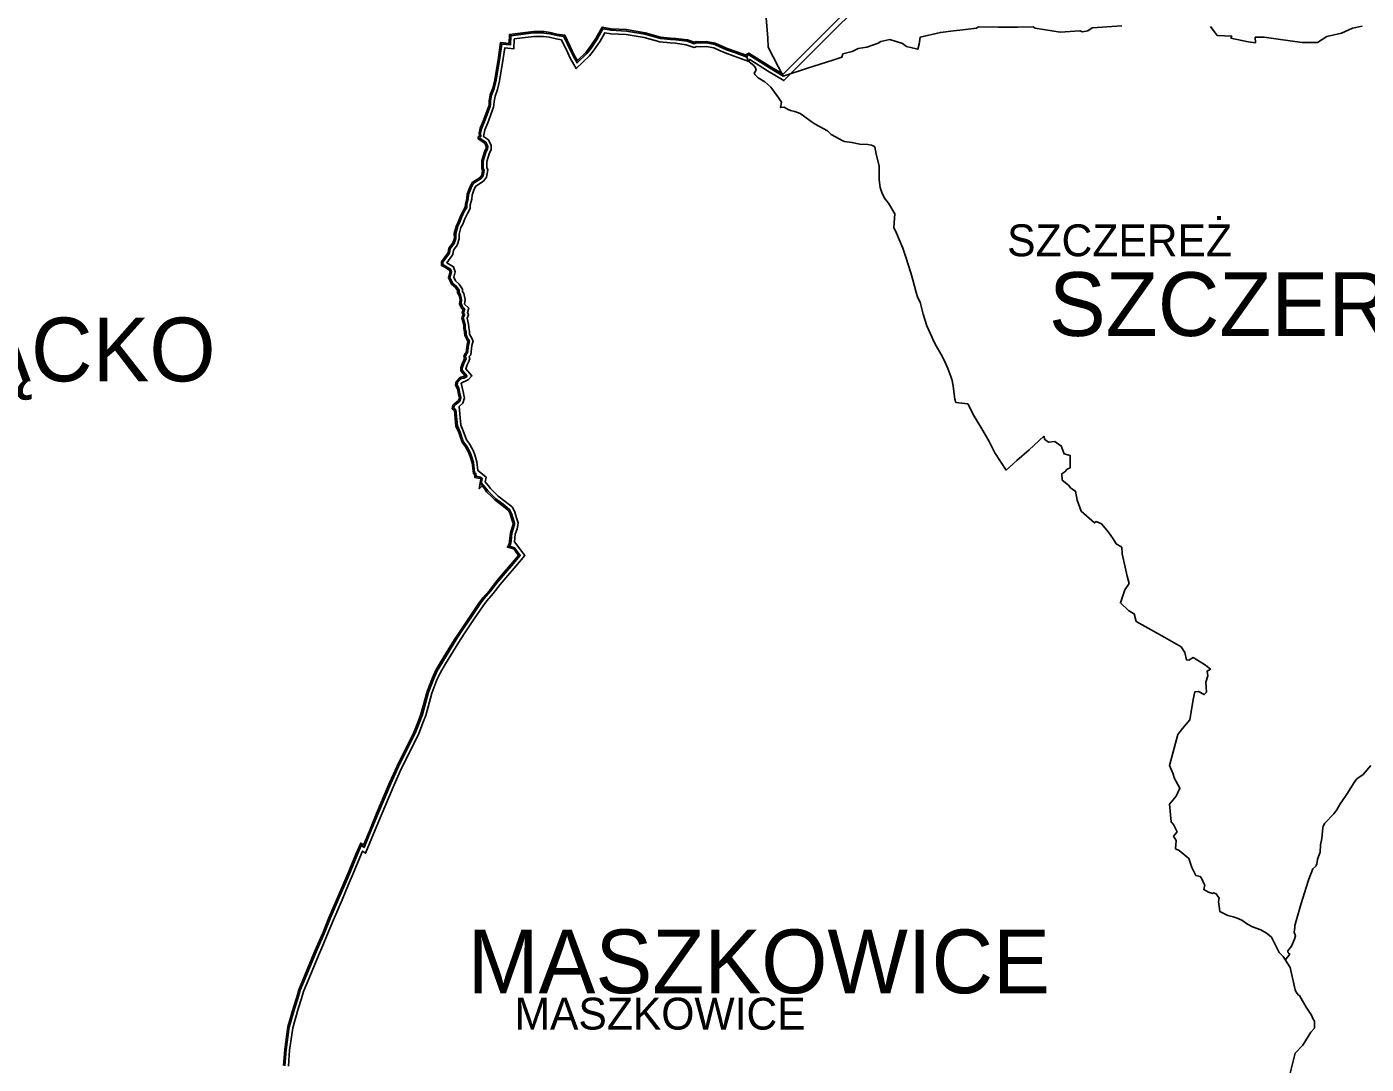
# Model space of a CAD drawing. Extents: x -562952 to -547638, y 190691 to 208158.
# Drawn here: x -556696 to -552912, y 199380 to 202309 of the extents above; entities that cross this region are included whole.
import ezdxf

# ---------------------------------------------------------------- set-up
doc = ezdxf.new("R2010")
doc.units = 0
for name, color, linetype in [('granica A_B', 7, 'Continuous'), ('granica_gminy', 7, 'Continuous'), ('granica_sołectwa', 7, 'Continuous'), ('nazwy miejscowości', 7, 'Continuous'), ('nazwy miejscowości DUŻE', 7, 'Continuous'), ('obwódka', 7, 'Continuous')]:
    doc.layers.add(name, color=color, linetype=linetype)

msp = doc.modelspace()

# ---------------------------------------------------------------- linework, layer by layer
at = {"layer": 'granica A_B'}
for points in [[(-555970.3, 199376.4), (-555967.1, 199421.4), (-555961.2, 199464.8), (-555958.2, 199485.8), (-555942.4, 199540.2), (-555933, 199569.1), (-555927.3, 199590), (-555909.1, 199633.1), (-555884.5, 199692.2), (-555872.4, 199720.8), (-555859.7, 199750.4), (-555842.2, 199793.3), (-555817.9, 199849.8), (-555800.4, 199891.1), (-555786.3, 199923.9), (-555765.3, 199974.4), (-555752.5, 200004.2), (-555744.8, 199998), (-555729, 200036), (-555708, 200087.9), (-555683.9, 200143.4), (-555671, 200174.2), (-555649.4, 200221.9), (-555630.3, 200260.3), (-555613, 200295.4), (-555602, 200316.1), (-555589.7, 200349.1), (-555582.2, 200368.6), (-555564.9, 200431.9), (-555550, 200470.8), (-555539.8, 200492.4), (-555525.4, 200517.5), (-555487.1, 200579.5), (-555471.8, 200602.5), (-555443.2, 200645.3), (-555418.4, 200681.8), (-555407.4, 200696.7), (-555388.8, 200717.8), (-555369, 200743.4), (-555347.7, 200768.8), (-555329.5, 200789.7), (-555306.9, 200816.6), (-555320.3, 200834.6), (-555338.2, 200839.7), (-555333, 200848.4), (-555331.9, 200857.8), (-555329.8, 200879.6), (-555324.3, 200895.7), (-555322.2, 200904.7), (-555321.9, 200906.8), (-555325.9, 200918.3), (-555329.9, 200933.4), (-555335.2, 200943.7), (-555352.6, 200957.7), (-555373.3, 200973.4), (-555381.2, 200981.2), (-555396.7, 200996.3), (-555403.2, 201005), (-555409.6, 201012.9), (-555417.8, 201004.8), (-555413.3, 201031.9), (-555415.5, 201033.6), (-555430, 201036.8), (-555431.3, 201045.7), (-555434.3, 201047.7), (-555438.1, 201078.2), (-555443.6, 201095.9), (-555446.9, 201105.1), (-555451.4, 201114.8), (-555456.9, 201123.2), (-555466.3, 201136.5), (-555475.7, 201163), (-555483.4, 201181), (-555487.8, 201225.3), (-555494.3, 201230.7), (-555492.4, 201240.4), (-555485.4, 201246.1), (-555476.2, 201254.1), (-555473.6, 201261.7), (-555474.6, 201265.4), (-555476.2, 201271.9), (-555479.3, 201287.2), (-555484.6, 201296.8), (-555482.8, 201307.7), (-555474.6, 201316.5), (-555469.7, 201319.3), (-555462.3, 201321.1), (-555457.2, 201323.3), (-555457.2, 201323.3), (-555469.6, 201337.8), (-555469.7, 201346.1), (-555464.9, 201359.8), (-555461.1, 201367.4), (-555459.2, 201372.2), (-555461, 201379.3), (-555456.5, 201387.2), (-555455, 201388.8), (-555452.2, 201411.8), (-555449.8, 201420.6), (-555454.1, 201427.8), (-555458.6, 201438), (-555458.9, 201446.9), (-555461.3, 201458.5), (-555461.5, 201467), (-555466.8, 201487.2), (-555463.4, 201495.8), (-555466, 201501.9), (-555463.2, 201510.4), (-555467.6, 201514.4), (-555473, 201527.1), (-555471.4, 201538.2), (-555474.5, 201550.3), (-555478.7, 201557.8), (-555478.7, 201564.2), (-555484.5, 201573), (-555496.2, 201582.4), (-555504.6, 201600.8), (-555499.9, 201616.5), (-555502, 201622), (-555514.8, 201629.8), (-555524.5, 201635.2), (-555524.7, 201645.7), (-555505.8, 201671.6), (-555503.9, 201683.5), (-555492.5, 201699.2), (-555488, 201712.1), (-555488.1, 201724.9), (-555482.3, 201747.9), (-555476.9, 201757.3), (-555471.5, 201771.8), (-555463.3, 201788.9), (-555457, 201799.6), (-555456.9, 201808.1), (-555452.7, 201824.2), (-555451.7, 201836.2), (-555444.6, 201856), (-555437.7, 201869), (-555415.4, 201883.4), (-555410.7, 201890.1), (-555408, 201903.3), (-555410.3, 201908.9), (-555410.1, 201931.1), (-555401.5, 201958.5), (-555398.2, 201964.9), (-555397.8, 201971.1), (-555402.3, 201980.1), (-555420.3, 201992.3), (-555420.3, 201997.9), (-555417, 202001.1), (-555417.8, 202008.5), (-555415, 202022.2), (-555406.4, 202042.7), (-555390.9, 202085.1), (-555390, 202090.3), (-555389.7, 202099), (-555386.5, 202116.6), (-555379.4, 202135.7), (-555373.8, 202159.2), (-555363.7, 202222), (-555357.5, 202264.4), (-555333.4, 202262), (-555332.4, 202286.9), (-555264.7, 202295.7), (-555249.4, 202295.9), (-555234.5, 202295.3), (-555217.4, 202293), (-555198.1, 202288.5), (-555175.8, 202285.2), (-555155.2, 202241.3), (-555148.2, 202227.3), (-555140.5, 202213.5), (-555116.6, 202236.5), (-555106.7, 202248.1), (-555088.1, 202275.9), (-555070.5, 202307.7), (-555044.7, 202303.2), (-555001.2, 202300.8), (-554948.9, 202292), (-554905.2, 202280), (-554877, 202277.1), (-554862, 202276.2), (-554829.6, 202272), (-554810.6, 202265.4), (-554804.5, 202267.6), (-554791.6, 202266.3), (-554776.2, 202267.3), (-554750.8, 202262.8), (-554734.7, 202255.2), (-554717.6, 202247.9), (-554692.7, 202238.8), (-554663.4, 202228.3), (-554661.7, 202231.8), (-554656, 202234.7), (-554595.9, 202196.5), (-554559.4, 202174.8), (-554225.8, 202508.4)], [(-555956.5, 199374.3), (-555953.2, 199420), (-555947.3, 199462.8), (-555944.4, 199482.9), (-555929, 199536.1), (-555919.6, 199565.1), (-555914, 199585.5), (-555896.2, 199627.6), (-555871.6, 199686.7), (-555859.5, 199715.3), (-555846.8, 199744.9), (-555829.3, 199787.9), (-555805, 199844.3), (-555787.5, 199885.6), (-555773.4, 199918.5), (-555747, 199981.9), (-555738.9, 199975.5), (-555716.1, 200030.7), (-555695, 200082.4), (-555671.1, 200137.9), (-555658.1, 200168.6), (-555636.8, 200215.9), (-555617.7, 200254), (-555600.5, 200289), (-555589.2, 200310.4), (-555576.6, 200344.2), (-555568.9, 200364.3), (-555551.6, 200427.5), (-555537.1, 200465.3), (-555527.4, 200485.9), (-555513.4, 200510.3), (-555475.3, 200571.9), (-555460.1, 200594.8), (-555431.6, 200637.5), (-555407, 200673.7), (-555396.5, 200687.9), (-555378, 200708.9), (-555358.1, 200734.6), (-555337.1, 200759.7), (-555318.9, 200780.5), (-555289.1, 200816), (-555318.1, 200855.1), (-555316, 200876.7), (-555310.9, 200891.9), (-555308.5, 200902), (-555307.5, 200908), (-555312.5, 200922.4), (-555316.8, 200938.5), (-555324.1, 200952.8), (-555344, 200968.8), (-555364.1, 200984), (-555371.4, 200991.2), (-555386.2, 201005.6), (-555392.2, 201013.6), (-555400.5, 201023.9), (-555398.2, 201037.8), (-555418.3, 201053.6), (-555418.4, 201054), (-555421.2, 201055.8), (-555424.4, 201081.1), (-555430.3, 201100.3), (-555434, 201110.5), (-555439.1, 201121.5), (-555445.3, 201131), (-555453.8, 201143), (-555462.7, 201168.1), (-555469.7, 201184.5), (-555474.8, 201236.7), (-555464.1, 201246), (-555458.9, 201261.3), (-555461.1, 201268.9), (-555462.5, 201274.9), (-555468.3, 201303.2), (-555448.8, 201311.7), (-555438.5, 201323.2), (-555455.8, 201343.3), (-555452, 201354.3), (-555448.3, 201361.6), (-555444.5, 201371.2), (-555446.1, 201377.8), (-555441.7, 201382.7), (-555438.5, 201409.1), (-555434.7, 201422.6), (-555441.6, 201434.2), (-555444.7, 201441.2), (-555444.9, 201448.6), (-555447.3, 201460.2), (-555447.6, 201469), (-555452.1, 201486.3), (-555448.3, 201496), (-555451.1, 201502.5), (-555447.1, 201514.7), (-555459.1, 201525.6), (-555457.1, 201538.9), (-555461.4, 201555.6), (-555464.7, 201561.5), (-555464.7, 201568.4), (-555474, 201582.5), (-555484.8, 201591.2), (-555489.7, 201601.8), (-555485.2, 201617.1), (-555490.6, 201631.4), (-555509.4, 201642.9), (-555492.4, 201666.1), (-555490.6, 201678), (-555479.9, 201692.6), (-555474, 201709.9), (-555474.1, 201723.2), (-555469.2, 201742.6), (-555464.2, 201751.4), (-555458.6, 201766.4), (-555451, 201782.2), (-555443, 201795.6), (-555442.9, 201806.2), (-555438.8, 201821.8), (-555437.9, 201833.2), (-555431.7, 201850.4), (-555427, 201859.2), (-555405.5, 201873.1), (-555397.6, 201884.4), (-555393.4, 201904.7), (-555396.3, 201911.6), (-555396.1, 201928.9), (-555388.5, 201953.2), (-555384.4, 201961.1), (-555383.6, 201974), (-555391.4, 201989.6), (-555405.5, 201999.1), (-555401.5, 202018), (-555393.3, 202037.6), (-555377.3, 202081.5), (-555376.1, 202088.9), (-555375.7, 202097.5), (-555373, 202112.9), (-555366, 202131.6), (-555360.1, 202156.5), (-555349.9, 202219.8), (-555345.6, 202249.2), (-555320, 202246.6), (-555318.9, 202274.5), (-555263.7, 202281.7), (-555249.6, 202281.9), (-555235.8, 202281.3), (-555219.9, 202279.2), (-555200.7, 202274.8), (-555185.3, 202272.5), (-555167.8, 202235.2), (-555160.6, 202220.7), (-555143.8, 202190.8), (-555106.4, 202226.9), (-555095.5, 202239.7), (-555076.2, 202268.6), (-555063.1, 202292.2), (-555046.3, 202289.3), (-555002.8, 202286.8), (-554952, 202278.3), (-554907.8, 202266.2), (-554878.1, 202263.2), (-554863.4, 202262.2), (-554832.8, 202258.3), (-554810.6, 202250.6), (-554802.8, 202253.3), (-554791.8, 202252.3), (-554777, 202253.3), (-554755, 202249.3), (-554740.5, 202242.5), (-554722.8, 202234.9), (-554697.5, 202225.6), (-554656.5, 202210.9), (-554653.6, 202216.6), (-554603.3, 202184.6), (-554557.2, 202157.2), (-554220, 202494.4)]]:
    msp.add_lwpolyline(points, dxfattribs=at)
at = {"layer": 'granica_gminy'}
for points in [[(-554607, 202333.1), (-554602.3, 202278.1), (-554601.6, 202250.9), (-554558.8, 202169.8), (-554490, 202191.9), (-554418.6, 202214.9), (-554393.7, 202223.1), (-554390.1, 202232.4), (-554364.5, 202238.9), (-554346.8, 202247.9), (-554322.8, 202251.5), (-554290.4, 202262.5), (-554283.5, 202266.9), (-554257.7, 202272.9), (-554221.6, 202261.5), (-554211, 202253.3), (-554178.9, 202245.3), (-554175.3, 202260.2), (-554172, 202279.6), (-554114.7, 202293.2), (-554077.5, 202297.3), (-554051.4, 202299.9), (-554013.3, 202305), (-554007.8, 202308.9), (-553951.8, 202307.6), (-553896.2, 202308.1), (-553852.8, 202308.9), (-553847.1, 202305), (-553776.2, 202293.7), (-553721.3, 202297), (-553713.3, 202294.7), (-553698.4, 202297.5), (-553686.5, 202306), (-553602.2, 202312)], [(-553352.3, 202309.4), (-553333.1, 202284.1), (-553291.9, 202282.8), (-553294.2, 202276.9), (-553245.5, 202266.3), (-553225.1, 202263.7), (-553225.4, 202279.2), (-553200.6, 202279.2), (-553160.8, 202273.5), (-553093.3, 202264.5), (-553050.1, 202264.8), (-553023, 202281.5), (-552982.3, 202291.3), (-552950.9, 202305), (-552923.6, 202310.7)]]:
    msp.add_lwpolyline(points, dxfattribs=at)
at = {"layer": 'granica_sołectwa'}
for points in [[(-554558.8, 202169.8), (-554598, 202193.1), (-554656.2, 202230.1), (-554658.7, 202228.8), (-554661.4, 202223.3), (-554694, 202235), (-554719.1, 202244.2), (-554736.4, 202251.6), (-554752, 202258.9), (-554776.5, 202263.3), (-554791.7, 202262.3), (-554804, 202263.5), (-554810.6, 202261.2), (-554830.5, 202268.1), (-554862.4, 202272.2), (-554877.3, 202273.1), (-554905.9, 202276), (-554949.8, 202288.1), (-555001.6, 202296.8), (-555045.1, 202299.2), (-555068.4, 202303.3), (-555084.7, 202273.9), (-555103.5, 202245.7), (-555113.7, 202233.7), (-555141.4, 202207), (-555151.7, 202225.4), (-555158.8, 202239.6), (-555178.5, 202281.6), (-555198.8, 202284.6), (-555218.1, 202289.1), (-555234.9, 202291.3), (-555249.5, 202291.9), (-555264.5, 202291.7), (-555328.6, 202283.4), (-555329.6, 202257.6), (-555354.1, 202260.1), (-555359.8, 202221.4), (-555369.9, 202158.5), (-555375.6, 202134.6), (-555382.7, 202115.5), (-555385.7, 202098.5)], [(-554661.4, 202223.3), (-554657.8, 202213.9), (-554654.8, 202209.5), (-554642.4, 202200), (-554637, 202193.4), (-554635.8, 202186), (-554641.1, 202178), (-554639.4, 202173.9), (-554629.5, 202164.8), (-554610.9, 202153.4), (-554593.5, 202138.4), (-554591, 202135), (-554571.7, 202107.3), (-554563.6, 202095.9), (-554566.3, 202080.7), (-554556.5, 202082.4), (-554545.4, 202075.6), (-554538.6, 202072.5), (-554526.4, 202069.8), (-554511.2, 202064.1), (-554501.3, 202057.6), (-554479.7, 202041.4), (-554468.8, 202034.4), (-554434.3, 202015.4), (-554423.1, 202005.2), (-554390.6, 201987.1), (-554386.2, 201985), (-554364.8, 201982.5), (-554342.1, 201977.9), (-554320.4, 201976.6), (-554309.5, 201974.7), (-554304.6, 201972.5), (-554300.5, 201970.1)], [(-555385.7, 202098.5), (-555386, 202089.9), (-555387, 202084), (-555402.6, 202041.3), (-555411.1, 202021), (-555413.8, 202008.4), (-555412.8, 201999.6), (-555416.3, 201996.2), (-555416.3, 201994.4), (-555399.2, 201982.8), (-555393.8, 201972), (-555394.3, 201963.8), (-555397.8, 201957), (-555406.1, 201930.5), (-555406.3, 201909.7), (-555403.8, 201903.7), (-555406.9, 201888.5), (-555412.5, 201880.5), (-555434.6, 201866.2), (-555440.9, 201854.4), (-555447.7, 201835.4), (-555448.7, 201823.5), (-555452.9, 201807.6), (-555453, 201798.4), (-555459.8, 201787), (-555467.8, 201770.3), (-555473.3, 201755.7), (-555478.5, 201746.4), (-555484.1, 201724.4), (-555484, 201711.5), (-555488.9, 201697.3), (-555500.1, 201682), (-555501.9, 201670.1), (-555520.7, 201644.4), (-555520.5, 201637.6), (-555512.8, 201633.2), (-555498.8, 201624.7), (-555495.7, 201616.7), (-555500.3, 201601.1), (-555492.9, 201584.9), (-555481.5, 201575.7), (-555474.7, 201565.4), (-555474.7, 201558.9), (-555470.7, 201551.8), (-555467.3, 201538.4), (-555468.9, 201527.7), (-555464.3, 201516.8), (-555458.6, 201511.6), (-555461.7, 201502.1), (-555459.1, 201495.9), (-555462.6, 201486.9)], [(-554300.5, 201970.1), (-554296.2, 201949.4), (-554288.4, 201916.2), (-554288.4, 201895.1), (-554288.2, 201876.6), (-554285.1, 201855.3), (-554280.1, 201841.4), (-554272.5, 201825.1), (-554261.7, 201811.1), (-554244.1, 201780.7), (-554246.5, 201742.6), (-554238.9, 201726.2), (-554231.5, 201708.3), (-554221.4, 201684.3), (-554212.9, 201658.7), (-554198.1, 201614), (-554193.2, 201594.8), (-554183.2, 201558.6), (-554178.7, 201543.9), (-554172.4, 201531.2), (-554163.6, 201497.3), (-554153.6, 201464.9), (-554149, 201454.6), (-554139.5, 201433.9), (-554134.2, 201422.7), (-554126.7, 201408.1), (-554113, 201383.9), (-554103.2, 201365.4), (-554093.5, 201344.6), (-554085.3, 201321.6), (-554081.7, 201310), (-554079, 201293.8), (-554074, 201257.8), (-554074, 201257.7)], [(-555462.6, 201486.9), (-555457.5, 201467.6), (-555457.3, 201459), (-555454.9, 201447.4), (-555454.6, 201438.9), (-555450.5, 201429.7), (-555445.5, 201421.2), (-555448.3, 201411), (-555451.2, 201387), (-555453.3, 201384.8), (-555456.7, 201378.8), (-555455, 201371.9), (-555457.4, 201365.7), (-555461.2, 201358.2), (-555465.7, 201345.4), (-555465.6, 201339.3), (-555452.4, 201323.9), (-555452.5, 201322.6), (-555454.8, 201320), (-555461, 201317.3), (-555468.2, 201315.5), (-555472.1, 201313.3), (-555479.1, 201305.9), (-555480.4, 201297.5), (-555475.5, 201288.6), (-555472.3, 201272.8), (-555470.8, 201266.4), (-555469.4, 201261.6), (-555472.7, 201251.7), (-555482.8, 201243), (-555488.7, 201238.2), (-555489.9, 201232.2), (-555484, 201227.3), (-555479.5, 201182), (-555472, 201164.5), (-555462.8, 201138.4), (-555453.5, 201125.4), (-555447.9, 201116.7), (-555443.2, 201106.6), (-555439.8, 201097.1), (-555434.2, 201079), (-555430.6, 201050), (-555427.6, 201048.1), (-555426.5, 201040.1), (-555413.8, 201037.3), (-555409, 201033.6), (-555411.9, 201016.2), (-555409.2, 201018.8), (-555400.1, 201007.5), (-555393.7, 200998.9), (-555378.4, 200984), (-555370.6, 200976.4), (-555350.2, 200960.9), (-555332, 200946.3), (-555326.1, 200934.9), (-555322.1, 200919.5), (-555317.8, 200907.1)], [(-554074.1, 201257.9), (-554070.9, 201248.6), (-554037.5, 201244.2), (-554019.8, 201209.6), (-553995.5, 201169), (-553977.2, 201138.3), (-553961.5, 201105.7), (-553928.9, 201057.2), (-553898.8, 201084.8), (-553864.3, 201114.9), (-553822.9, 201152.8), (-553820, 201143.4), (-553809.2, 201136.5), (-553792.1, 201138.4), (-553778, 201127.4), (-553773.6, 201126), (-553765.3, 201103.1), (-553748.5, 201098.9), (-553748.8, 201063.8), (-553757, 201059.7), (-553763.7, 201052.5), (-553771.7, 201047.2), (-553770.8, 201029), (-553753.4, 201014.4), (-553746.8, 201006.7), (-553733.6, 200997.9), (-553728.6, 200972.2), (-553717, 200941), (-553679.2, 200908.3), (-553674.5, 200911.8), (-553659.5, 200905.2), (-553640, 200881.9), (-553626.8, 200863.3), (-553618.8, 200849.3), (-553602.2, 200839.5), (-553601.6, 200821.1), (-553592.7, 200782.8), (-553587.3, 200758.2), (-553582, 200736.9), (-553594.2, 200719.7), (-553606.3, 200682.4), (-553582.6, 200660.4), (-553567.8, 200651.2), (-553562.1, 200629.9), (-553528, 200610.6), (-553481.2, 200584.5), (-553434.6, 200558.1), (-553424.1, 200542.8), (-553420.2, 200521.4), (-553413.4, 200520.8)], [(-555317.8, 200907.1), (-555318.3, 200903.9), (-555320.5, 200894.6), (-555325.8, 200878.8), (-555327.9, 200857.3), (-555329.1, 200847.1), (-555332.1, 200842.1), (-555317.9, 200838.1), (-555301.8, 200816.4), (-555326.5, 200787.1), (-555344.7, 200766.2), (-555365.9, 200740.9), (-555385.7, 200715.2), (-555404.3, 200694.2), (-555415.1, 200679.5), (-555439.9, 200643.1), (-555468.4, 200600.3), (-555483.8, 200577.3), (-555521.9, 200515.4), (-555536.2, 200490.5), (-555546.3, 200469.3)], [(-553413.4, 200520.8), (-553400.6, 200527.9), (-553376.9, 200512.8), (-553365.9, 200506.3), (-553351.7, 200495.3), (-553361.4, 200489.9), (-553359.1, 200476.2), (-553365.3, 200458.4), (-553363.2, 200430.5), (-553369.5, 200423.3), (-553385.8, 200432.5), (-553395.9, 200431.6), (-553400.9, 200409.4), (-553410.4, 200352.1), (-553431.2, 200328.2), (-553443.9, 200310.4), (-553467.7, 200223.7), (-553458.8, 200201.5), (-553453.4, 200186.8), (-553438.3, 200159.2), (-553449.3, 200136.9), (-553467.4, 200113.7), (-553463.2, 200064.7), (-553456.1, 200057.2), (-553446.3, 200035.9), (-553456.4, 200023.4), (-553449, 200011.8), (-553450.8, 199988.1), (-553440.4, 199983), (-553413.1, 199960.8), (-553404.5, 199935.6), (-553393.2, 199913.1), (-553380.7, 199909.8), (-553376, 199903.3), (-553369.8, 199888.7), (-553368.3, 199886.8), (-553370.9, 199873.1), (-553357.4, 199865.9), (-553346.2, 199862.2), (-553343.9, 199863.9), (-553335.8, 199861.1), (-553327.4, 199848.5), (-553329.1, 199839.6), (-553325.5, 199811), (-553303.1, 199800.1), (-553288, 199795.7), (-553276.3, 199792.6), (-553263.4, 199787), (-553247.4, 199775.8), (-553233.7, 199768), (-553209.7, 199759.6), (-553194, 199749.8)], [(-555966.4, 199375.8), (-555963.1, 199421), (-555957.2, 199464.2), (-555954.2, 199485), (-555938.6, 199539.1), (-555929.1, 199567.9), (-555923.5, 199588.7), (-555905.4, 199631.5), (-555880.9, 199690.6), (-555868.7, 199719.2), (-555856, 199748.8), (-555838.5, 199791.7), (-555814.2, 199848.3), (-555796.7, 199889.6), (-555782.7, 199922.4), (-555761.6, 199972.8), (-555750.9, 199997.8), (-555743.1, 199991.6), (-555725.3, 200034.5), (-555704.3, 200086.3), (-555680.3, 200141.8), (-555667.3, 200172.6), (-555645.8, 200220.2), (-555626.7, 200258.5), (-555609.4, 200293.6), (-555598.3, 200314.5), (-555585.9, 200347.7), (-555578.4, 200367.4), (-555561.1, 200430.7), (-555546.3, 200469.3)], [(-553140.8, 199674.1), (-553128, 199690.9), (-553132.3, 199694.5), (-553133.6, 199700.5), (-553123.6, 199713.7), (-553114.9, 199733), (-553112, 199742.1), (-553115.8, 199753.2), (-553113.9, 199765.6), (-553114, 199771.4), (-553110.2, 199784.9), (-553095.9, 199834.1), (-553081.6, 199879.2), (-553074, 199902.2), (-553063.2, 199931.5), (-553054.1, 199938.7), (-553053.4, 199941), (-553051.7, 199945.8), (-553050, 199957.5), (-553049.4, 199959.1), (-553042.6, 199978.2), (-553041.1, 199999.8), (-553037.8, 200016.8), (-553034.5, 200047.6), (-553033.9, 200052.2), (-553028.9, 200060.4), (-553004, 200086.8), (-553004, 200086.8), (-552995, 200097.7), (-552985.3, 200114.7), (-552981.4, 200121.5), (-552967.2, 200142.3), (-552946.4, 200175.4), (-552938.8, 200185.3), (-552920.8, 200197.6), (-552898.7, 200223.3)], [(-553194, 199749.8), (-553185.4, 199743.6), (-553180.1, 199738.3), (-553158.3, 199695.3), (-553146.8, 199683.9), (-553127.2, 199652.8), (-553112.9, 199590), (-553110.3, 199583.7), (-553103.3, 199574.5), (-553100.8, 199573.8), (-553095.6, 199565.9), (-553082.1, 199540.6), (-553066.4, 199518.6)], [(-553066.4, 199518.6), (-553062.8, 199509.2), (-553058.3, 199501.2), (-553057.8, 199481.8), (-553068.8, 199470.2), (-553091.4, 199433.5), (-553112.6, 199411.3), (-553127.4, 199350.8)]]:
    msp.add_lwpolyline(points, dxfattribs=at)
at = {"layer": 'obwódka'}
for points in [[(-554607, 202333.1), (-554602.3, 202278.1), (-554601.6, 202250.9), (-554558.8, 202169.8), (-554490, 202191.9), (-554418.6, 202214.9), (-554393.7, 202223.1), (-554390.1, 202232.4), (-554364.5, 202238.9), (-554346.8, 202247.9), (-554322.8, 202251.5), (-554290.4, 202262.5), (-554283.5, 202266.9), (-554257.7, 202272.9), (-554221.6, 202261.5), (-554211, 202253.3), (-554178.9, 202245.3), (-554175.3, 202260.2), (-554172, 202279.6), (-554114.7, 202293.2), (-554077.5, 202297.3), (-554051.4, 202299.9), (-554013.3, 202305), (-554007.8, 202308.9), (-553951.8, 202307.6), (-553896.2, 202308.1), (-553852.8, 202308.9), (-553847.1, 202305), (-553776.2, 202293.7), (-553721.3, 202297), (-553713.3, 202294.7), (-553698.4, 202297.5), (-553686.5, 202306), (-553602.2, 202312)], [(-553352.3, 202309.4), (-553333.1, 202284.1), (-553291.9, 202282.8), (-553294.2, 202276.9), (-553245.5, 202266.3), (-553225.1, 202263.7), (-553225.4, 202279.2), (-553200.6, 202279.2), (-553160.8, 202273.5), (-553093.3, 202264.5), (-553050.1, 202264.8), (-553023, 202281.5), (-552982.3, 202291.3), (-552950.9, 202305), (-552923.6, 202310.7)]]:
    msp.add_lwpolyline(points, dxfattribs=at)

# ---------------------------------------------------------------- texts
at = {"layer": 'nazwy miejscowości'}
for s, p in [('SZCZEREŻ', (-553926.5, 201661)), ('MASZKOWICE', (-555318, 199477.8))]:
    msp.add_text(s, height=90, dxfattribs=at).set_placement(p)
at = {"layer": 'nazwy miejscowości DUŻE'}
for s, p in [('SZCZEREŻ', (-553808.4, 201436)), ('ŁĄCKO', (-556978.3, 201307.8)), ('MASZKOWICE', (-555450.4, 199580.3))]:
    msp.add_text(s, height=180, dxfattribs=at).set_placement(p)

doc.saveas('drawing.dxf')
